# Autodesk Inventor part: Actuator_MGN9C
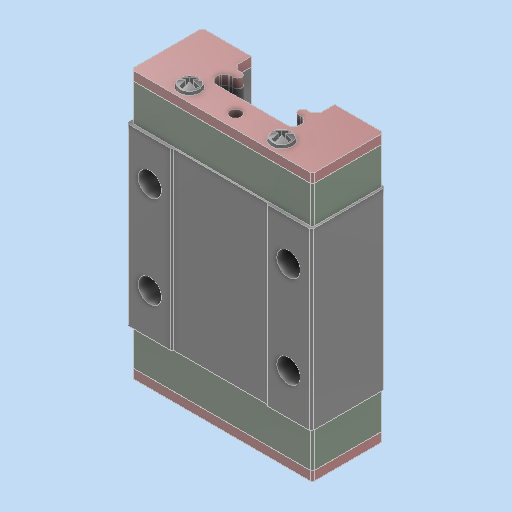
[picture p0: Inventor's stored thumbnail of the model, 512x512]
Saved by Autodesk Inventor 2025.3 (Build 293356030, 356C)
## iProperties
Created: 2000-04
Part Number: Actuator_MGN9C
Material: Generico
Document SubType Name: Modeling
Designer: R5800u
Density: 1 g/cm^3
Appearance: Default
Sending System: SolidWorks 2021
Last Author: Albert
Last Saved: 2021-07-28
Author: R5800u
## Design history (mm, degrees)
feature "Импортированный1"
node "Piano di lavoro1"
node "Solido1"
